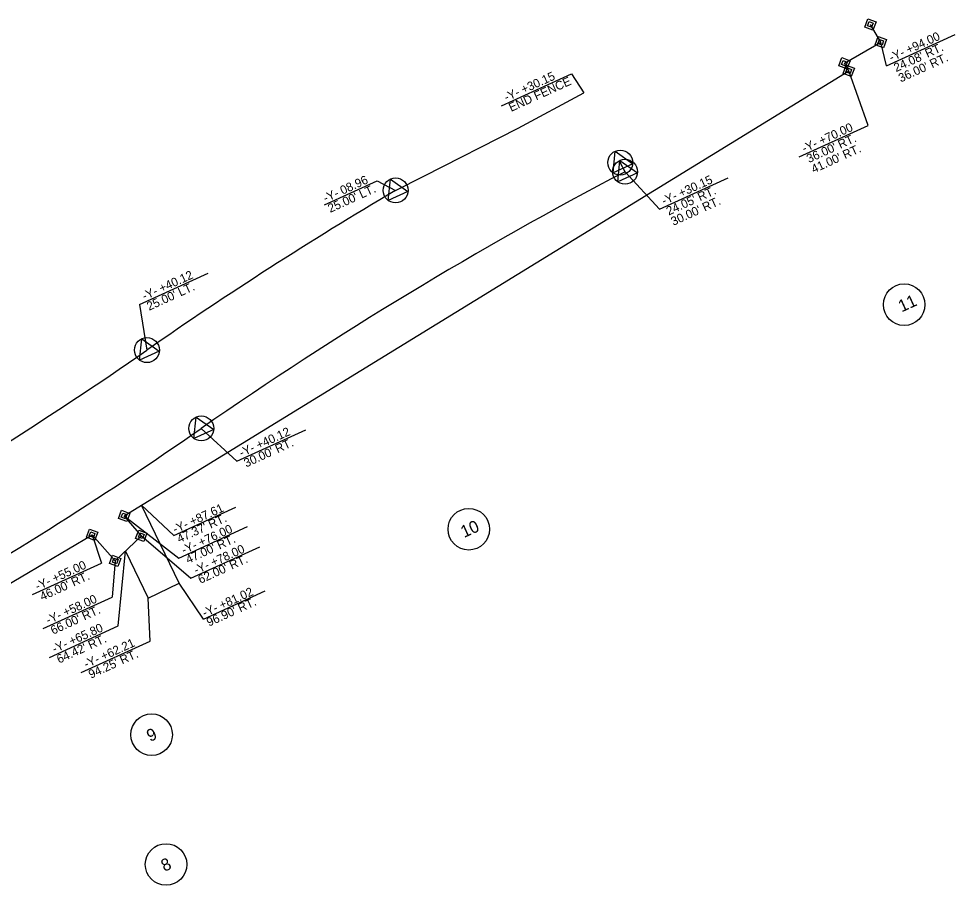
# Model space of a CAD drawing. Extents: x 2242607 to 2250377, y 661355 to 663917.
# Drawn here: x 2249836 to 2250377, y 663377 to 663877 of the extents above; entities that cross this region are included whole.
import ezdxf

# ---------------------------------------------------------------- set-up
doc = ezdxf.new("R2010")
doc.units = 0
for name, color, linetype in [('Prop Easement Construction', 7, 'Continuous'), ('Prop Easement Construction Station Offsets', 7, 'Continuous'), ('Prop Easement Permanent Utility', 7, 'Continuous'), ('Prop Easement Permanent Utility Station Offsets', 7, 'Continuous'), ('Prop Fence Woven Wire', 7, 'Continuous'), ('Prop Parcel Number CELL', 7, 'Continuous'), ('Prop ROW CA Lines', 7, 'Continuous'), ('Prop ROW Marker CELL', 7, 'Continuous'), ('Prop ROW Permanent Easement CELL', 7, 'Continuous'), ('Prop ROW RW Lines', 7, 'Continuous'), ('Prop ROW Station Offsets', 7, 'Continuous')]:
    doc.layers.add(name, color=color, linetype=linetype)

msp = doc.modelspace()

# ---------------------------------------------------------------- linework, layer by layer
at = {"layer": 'Prop Easement Construction'}
for p, q in [((2249928.8, 663551.27), (2249907.21, 663596.35)), ((2249897.86, 663569.85), (2249910.95, 663542.79)), ((2249910.95, 663542.79), (2249928.8, 663551.27))]:
    msp.add_line(p, q, dxfattribs=at)
at = {"layer": 'Prop Easement Construction Station Offsets'}
for p, q in [((2249925.76, 663578.92), (2249907.21, 663596.35)), ((2249925.76, 663578.92), (2249961.52, 663595.21)), ((2249893.74, 663526.63), (2249897.86, 663569.85)), ((2249942.85, 663530.64), (2249928.8, 663551.27)), ((2249912.09, 663517.88), (2249910.95, 663542.79)), ((2249942.85, 663530.64), (2249978.61, 663546.93)), ((2249853.94, 663508.49), (2249893.74, 663526.63)), ((2249872.29, 663499.75), (2249912.09, 663517.88))]:
    msp.add_line(p, q, dxfattribs=at)
at = {"layer": 'Prop Easement Permanent Utility'}
for p, q in [((2250334, 663863.57), (2250328, 663873.87)), ((2250313.02, 663851.43), (2250334, 663863.57)), ((2250315.51, 663847.09), (2250313.02, 663851.43)), ((2249897.1, 663590.15), (2250315.51, 663847.09)), ((2249907.04, 663578.72), (2249897.1, 663590.15)), ((2249740.95, 663497.53), (2249878.58, 663579.34)), ((2249878.58, 663579.34), (2249891.98, 663564.17)), ((2249891.98, 663564.17), (2249907.04, 663578.72))]:
    msp.add_line(p, q, dxfattribs=at)
at = {"layer": 'Prop Easement Permanent Utility Station Offsets'}
for p, q in [((2250337.24, 663849.89), (2250377.03, 663868.02)), ((2250337.24, 663849.89), (2250334, 663863.57)), ((2250326.74, 663815.51), (2250315.51, 663847.09)), ((2250286.94, 663797.38), (2250326.74, 663815.51)), ((2249897.1, 663590.15), (2249928.63, 663565.85)), ((2249928.63, 663565.85), (2249968.42, 663583.99)), ((2249878.58, 663579.34), (2249884.01, 663562.86)), ((2249907.04, 663578.72), (2249935.62, 663554.28)), ((2249935.62, 663554.28), (2249975.42, 663572.42)), ((2249844.21, 663544.72), (2249884.01, 663562.86)), ((2249891.98, 663564.17), (2249890.23, 663543.28)), ((2249850.43, 663525.14), (2249890.23, 663543.28))]:
    msp.add_line(p, q, dxfattribs=at)
at = {"layer": 'Prop Fence Woven Wire'}
msp.add_lwpolyline([(2250053.84, 663778.05), (2250070.09, 663786.24), (2250124.62, 663814.07), (2250162.54, 663834.42)], dxfattribs=at)
for centre, radius, start, end in [((2251237.28, 661776.78), 2325, 120.5976, 124.80379), ((2248611.75, 665553.89), 2275, 294.41783, 304.80379)]:
    msp.add_arc(centre, radius, start, end, dxfattribs=at)
at = {"layer": 'Prop Parcel Number CELL'}
for p, q in [((2250347.53, 663712.11), (2250347.53, 663712.11)), ((2250096.12, 663582.48), (2250096.12, 663582.48)), ((2249912.96, 663463.89), (2249912.96, 663463.89)), ((2249921.3, 663388.98), (2249921.3, 663388.98))]:
    msp.add_line(p, q, dxfattribs=at)
for centre in [(2250347.53, 663712.11), (2250096.12, 663582.48), (2249912.96, 663463.89), (2249921.3, 663388.98)]:
    msp.add_circle(centre, 12, dxfattribs=at)
at = {"layer": 'Prop ROW CA Lines'}
for centre, radius, start, end in [((2251237.28, 661776.78), 2325, 120.5976, 124.80379), ((2248611.75, 665553.89), 2275, 294.41783, 304.80379)]:
    msp.add_arc(centre, radius, start, end, dxfattribs=at)
at = {"layer": 'Prop ROW Marker CELL'}
for p, q in [((2250328, 663873.87), (2250328, 663873.87)), ((2250334, 663863.57), (2250334, 663863.57)), ((2250313.02, 663851.43), (2250313.02, 663851.43)), ((2250315.51, 663847.09), (2250315.51, 663847.09)), ((2250183.59, 663794.12), (2250183.59, 663794.12)), ((2250186.34, 663788.85), (2250186.34, 663788.85)), ((2250053.84, 663778.05), (2250053.84, 663778.05)), ((2249910.25, 663685.86), (2249910.25, 663685.86)), ((2249941.64, 663640.7), (2249941.64, 663640.7)), ((2249897.1, 663590.15), (2249897.1, 663590.15)), ((2249878.58, 663579.34), (2249878.58, 663579.34)), ((2249907.04, 663578.72), (2249907.04, 663578.72)), ((2249891.98, 663564.17), (2249891.98, 663564.17))]:
    msp.add_line(p, q, dxfattribs=at)
for points in [[(2250179.4, 663788.25), (2250180.6, 663800.67), (2250190.77, 663793.43)], [(2250182.15, 663782.98), (2250183.36, 663795.4), (2250193.52, 663788.16)], [(2250049.65, 663772.18), (2250050.86, 663784.6), (2250061.02, 663777.37)], [(2249906.05, 663679.99), (2249907.26, 663692.41), (2249917.43, 663685.18)], [(2249937.44, 663634.83), (2249938.65, 663647.25), (2249948.82, 663640.01)]]:
    msp.add_lwpolyline(points, close=True, dxfattribs=at)
for centre in [(2250183.59, 663794.12), (2250186.34, 663788.85), (2250053.84, 663778.05), (2249910.25, 663685.86), (2249941.64, 663640.7)]:
    msp.add_circle(centre, 7.2, dxfattribs=at)
at = {"layer": 'Prop ROW Permanent Easement CELL'}
for points in [[(2250326.51, 663877.14), (2250331.27, 663875.36), (2250329.49, 663870.59), (2250324.72, 663872.37)], [(2250327.25, 663875.5), (2250329.64, 663874.61), (2250328.74, 663872.23), (2250326.36, 663873.12)], [(2250332.51, 663866.85), (2250337.28, 663865.07), (2250335.5, 663860.3), (2250330.73, 663862.08)], [(2250333.26, 663865.21), (2250335.64, 663864.32), (2250334.75, 663861.94), (2250332.37, 663862.83)], [(2250311.53, 663854.7), (2250316.29, 663852.92), (2250314.51, 663848.15), (2250309.74, 663849.93)], [(2250312.27, 663853.06), (2250314.66, 663852.17), (2250313.76, 663849.79), (2250311.38, 663850.68)], [(2250314.02, 663850.37), (2250318.78, 663848.58), (2250317, 663843.82), (2250312.23, 663845.6)], [(2250314.76, 663848.73), (2250317.15, 663847.84), (2250316.25, 663845.45), (2250313.87, 663846.34)], [(2249895.61, 663593.42), (2249900.38, 663591.64), (2249898.6, 663586.87), (2249893.83, 663588.66)], [(2249896.36, 663591.79), (2249898.74, 663590.9), (2249897.85, 663588.51), (2249895.47, 663589.4)], [(2249877.09, 663582.61), (2249881.86, 663580.83), (2249880.07, 663576.06), (2249875.31, 663577.84)], [(2249877.83, 663580.97), (2249880.22, 663580.08), (2249879.33, 663577.7), (2249876.94, 663578.59)], [(2249905.54, 663582), (2249910.31, 663580.22), (2249908.53, 663575.45), (2249903.76, 663577.23)], [(2249906.29, 663580.36), (2249908.68, 663579.47), (2249907.78, 663577.09), (2249905.4, 663577.98)], [(2249890.48, 663567.45), (2249895.25, 663565.66), (2249893.47, 663560.9), (2249888.7, 663562.68)], [(2249891.23, 663565.81), (2249893.62, 663564.92), (2249892.72, 663562.53), (2249890.34, 663563.43)]]:
    msp.add_lwpolyline(points, close=True, dxfattribs=at)
at = {"layer": 'Prop ROW RW Lines'}
msp.add_line((2250186.34, 663788.85), (2250183.59, 663794.12), dxfattribs=at)
for centre, radius, start, end in [((2251237.28, 661776.78), 2270, 117.57881, 124.80379), ((2248611.75, 665553.89), 2330, 294.41783, 304.80379)]:
    msp.add_arc(centre, radius, start, end, dxfattribs=at)
at = {"layer": 'Prop ROW Station Offsets'}
for p, q in [((2250114.95, 663826.93), (2250155.46, 663845.39)), ((2250155.46, 663845.39), (2250162.54, 663834.42)), ((2250206.17, 663767.24), (2250186.34, 663788.85)), ((2250012.84, 663769.73), (2250043.31, 663783.61)), ((2250043.31, 663783.61), (2250053.84, 663778.05)), ((2250206.17, 663767.24), (2250245.97, 663785.38)), ((2249905.91, 663712.15), (2249945.71, 663730.28)), ((2249905.91, 663712.15), (2249910.25, 663685.86)), ((2249962.24, 663621.8), (2249941.64, 663640.7)), ((2249962.24, 663621.8), (2250002.04, 663639.94))]:
    msp.add_line(p, q, dxfattribs=at)

# ---------------------------------------------------------------- texts
at = {"layer": 'Prop Easement Construction Station Offsets'}
for s, p in [('-Y- +87.61', (2249926.52, 663579.96)), ("47.37' RT.", (2249929, 663574.5)), ('-Y- +81.02', (2249943.61, 663531.68)), ("96.90' RT.", (2249946.09, 663526.22)), ('-Y- +65.80', (2249856.86, 663510.87)), ("64.42' RT.", (2249859.57, 663504.9)), ('-Y- +62.21', (2249875.21, 663502.13)), ("94.25' RT.", (2249877.92, 663496.16))]:
    msp.add_text(s, height=5, rotation=24.4301, dxfattribs=at).set_placement(p)
at = {"layer": 'Prop Easement Permanent Utility Station Offsets'}
for s, p in [('-Y- +94.00', (2250340.16, 663852.27)), ("24.08' RT.", (2250342.87, 663846.3)), ("36.00' RT.", (2250345.58, 663840.33)), ('-Y- +70.00', (2250289.86, 663799.76)), ("36.00' RT.", (2250292.57, 663793.79)), ("41.00' RT.", (2250295.28, 663787.82)), ('-Y- +76.00', (2249931.58, 663567.95)), ("47.00' RT.", (2249934.06, 663562.48)), ('-Y- +78.00', (2249938.67, 663556.37)), ('-Y- +55.00', (2249847.13, 663547.1)), ("62.00' RT.", (2249941.16, 663550.91)), ("46.00' RT.", (2249849.84, 663541.14)), ('-Y- +58.00', (2249853.35, 663527.52)), ("66.00' RT.", (2249856.06, 663521.55))]:
    msp.add_text(s, height=5, rotation=24.4301, dxfattribs=at).set_placement(p)
at = {"layer": 'Prop Parcel Number CELL'}
for s, p in [('11', (2250346.06, 663707.6)), ('10', (2250093.39, 663577.39)), ('9', (2249912.05, 663459.63)), ('8', (2249920.34, 663384.7))]:
    msp.add_text(s, height=7, rotation=24.4979, dxfattribs=at).set_placement(p)
at = {"layer": 'Prop ROW Station Offsets'}
for s, p in [('-Y- +30.15', (2250117.86, 663829.31)), ('END FENCE', (2250120.58, 663823.34)), ('-Y- 08.96', (2250013.42, 663771.04)), ('-Y- +30.15', (2250208.83, 663769.5)), ("25.00' LT.", (2250016.13, 663765.07)), ("24.05' RT.", (2250211.54, 663763.54)), ("30.00' RT.", (2250214.25, 663757.57)), ('-Y- +40.12', (2249908.83, 663714.53)), ("25.00' LT.", (2249911.54, 663708.56)), ('-Y- +40.12', (2249964.9, 663624.06)), ("30.00' RT.", (2249967.61, 663618.1))]:
    msp.add_text(s, height=5, rotation=24.4301, dxfattribs=at).set_placement(p)

doc.saveas('drawing.dxf')
